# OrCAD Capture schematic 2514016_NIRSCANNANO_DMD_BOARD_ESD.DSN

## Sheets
1 PAGE-01  TITLE: title: ESD, Mobile Spectroscopy DMD Board
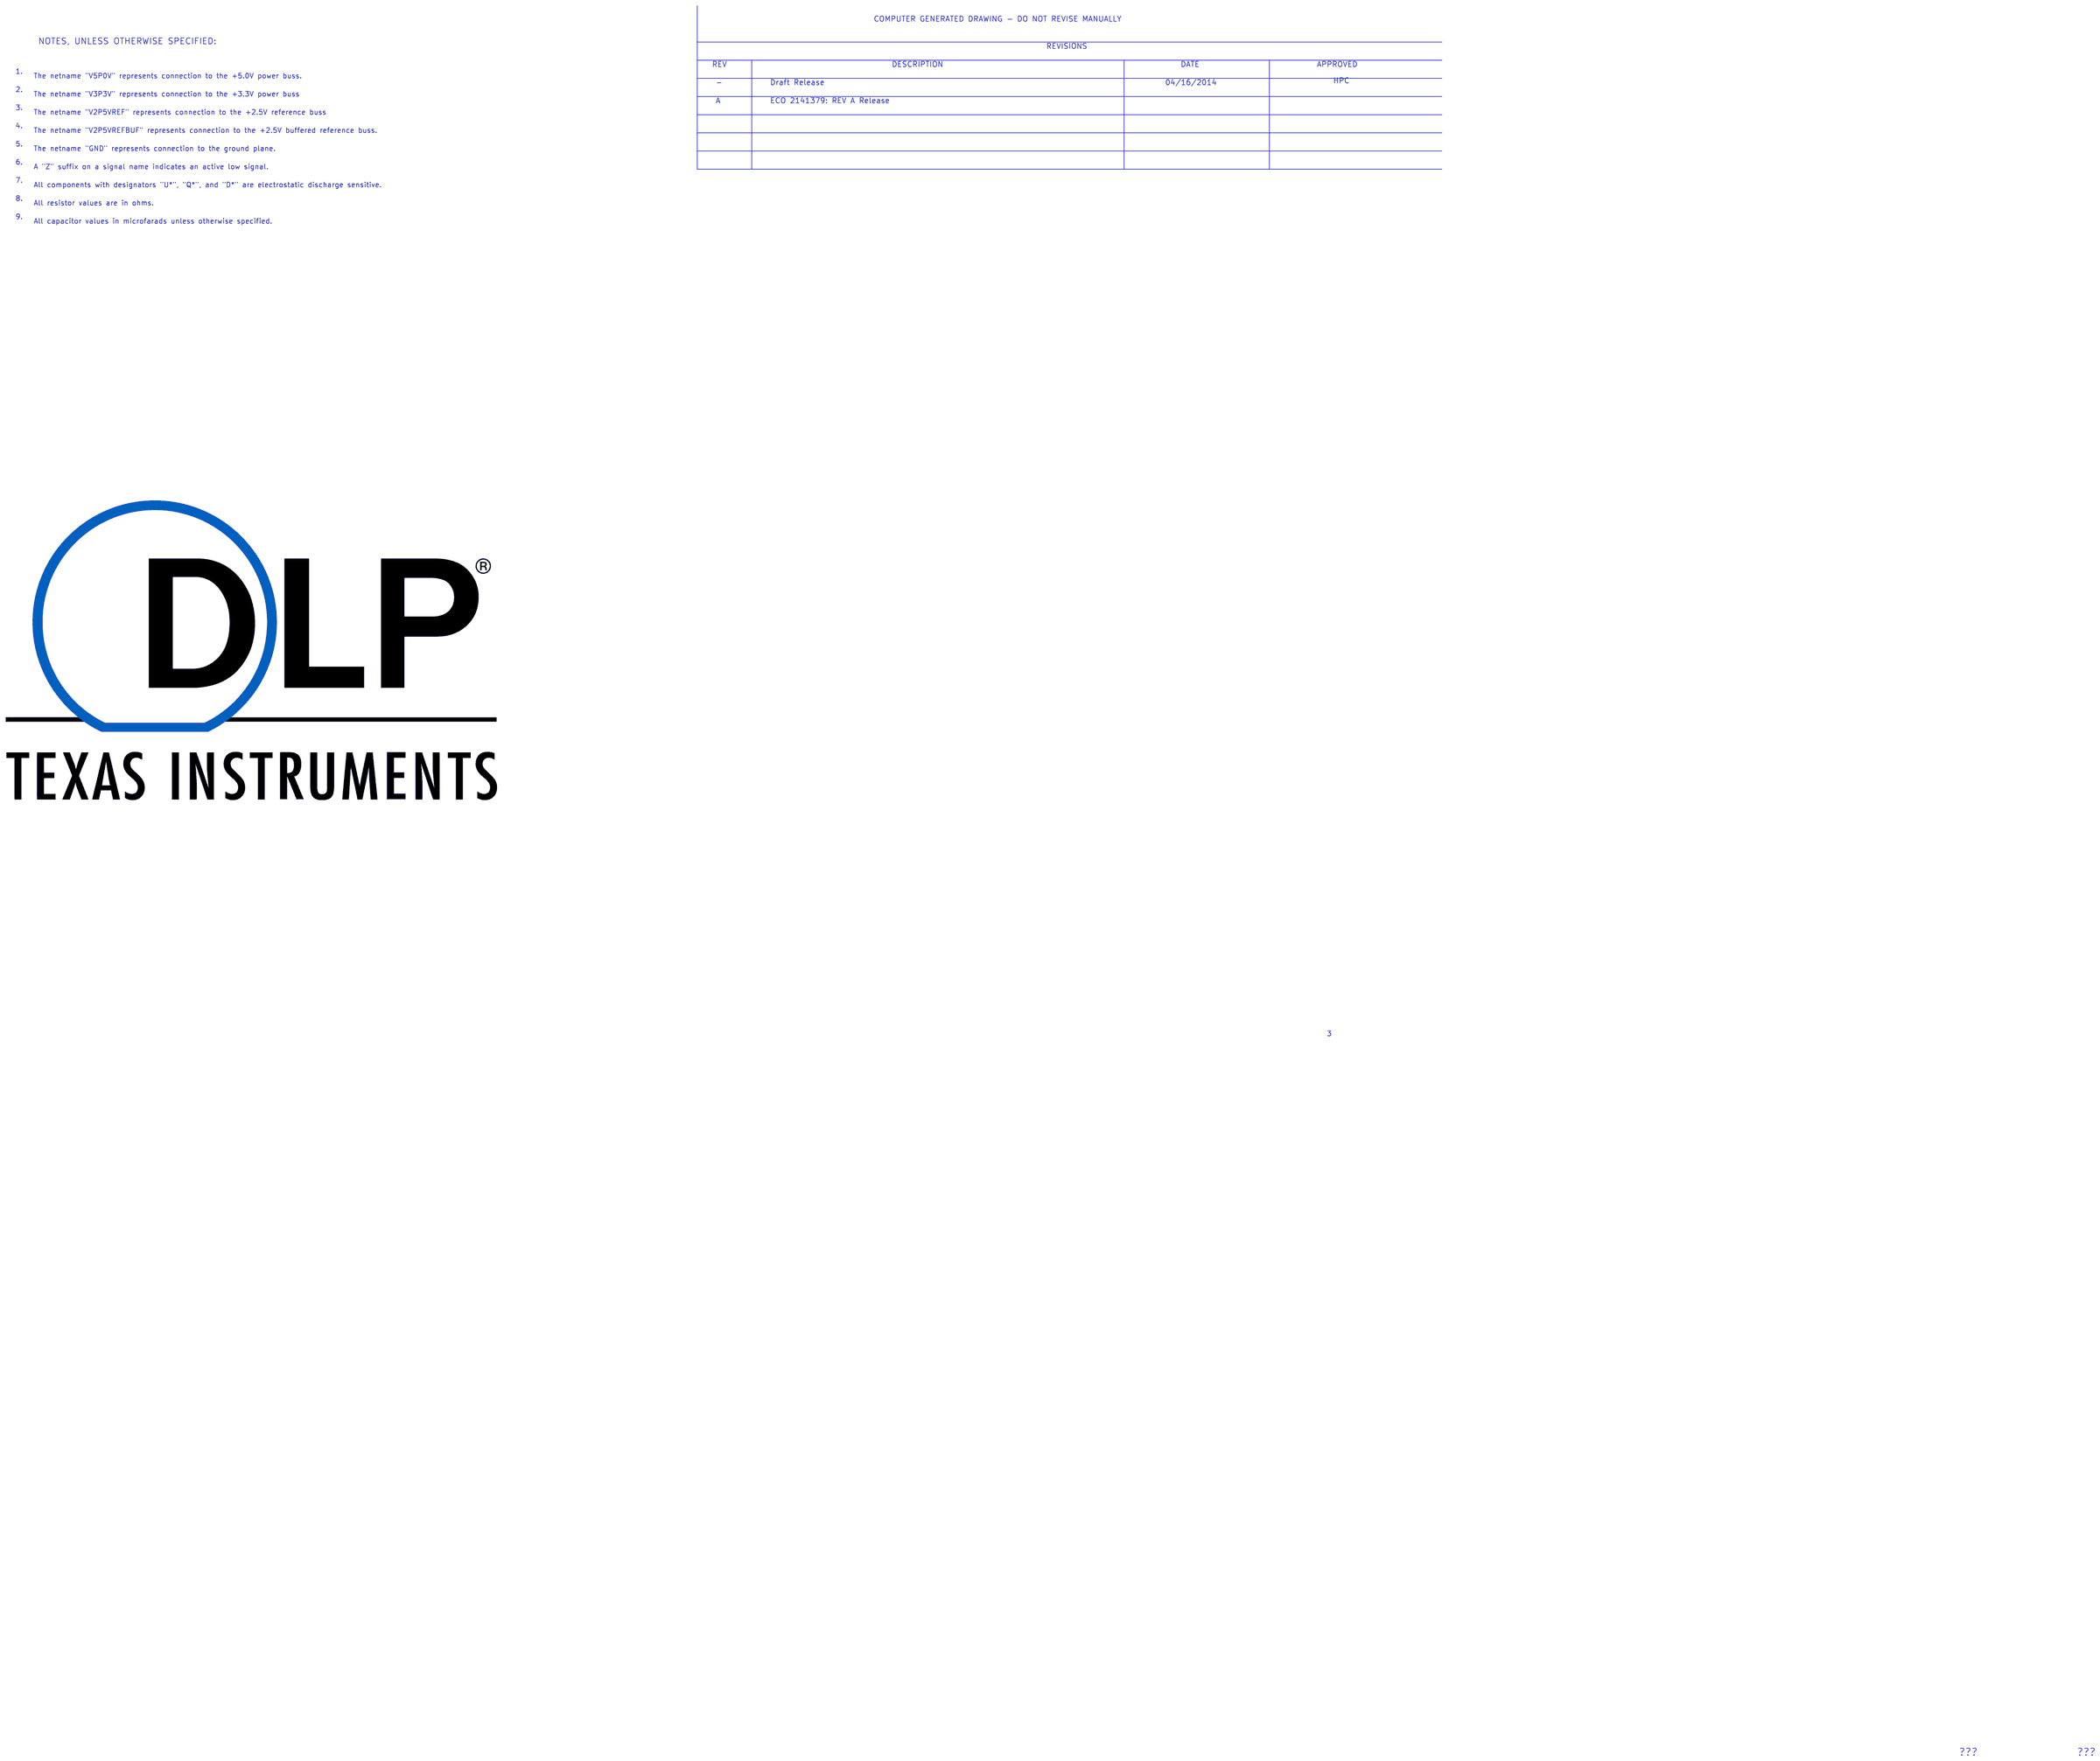
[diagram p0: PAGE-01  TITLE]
2 PAGE-02 s244 WVGA DMD: size A3
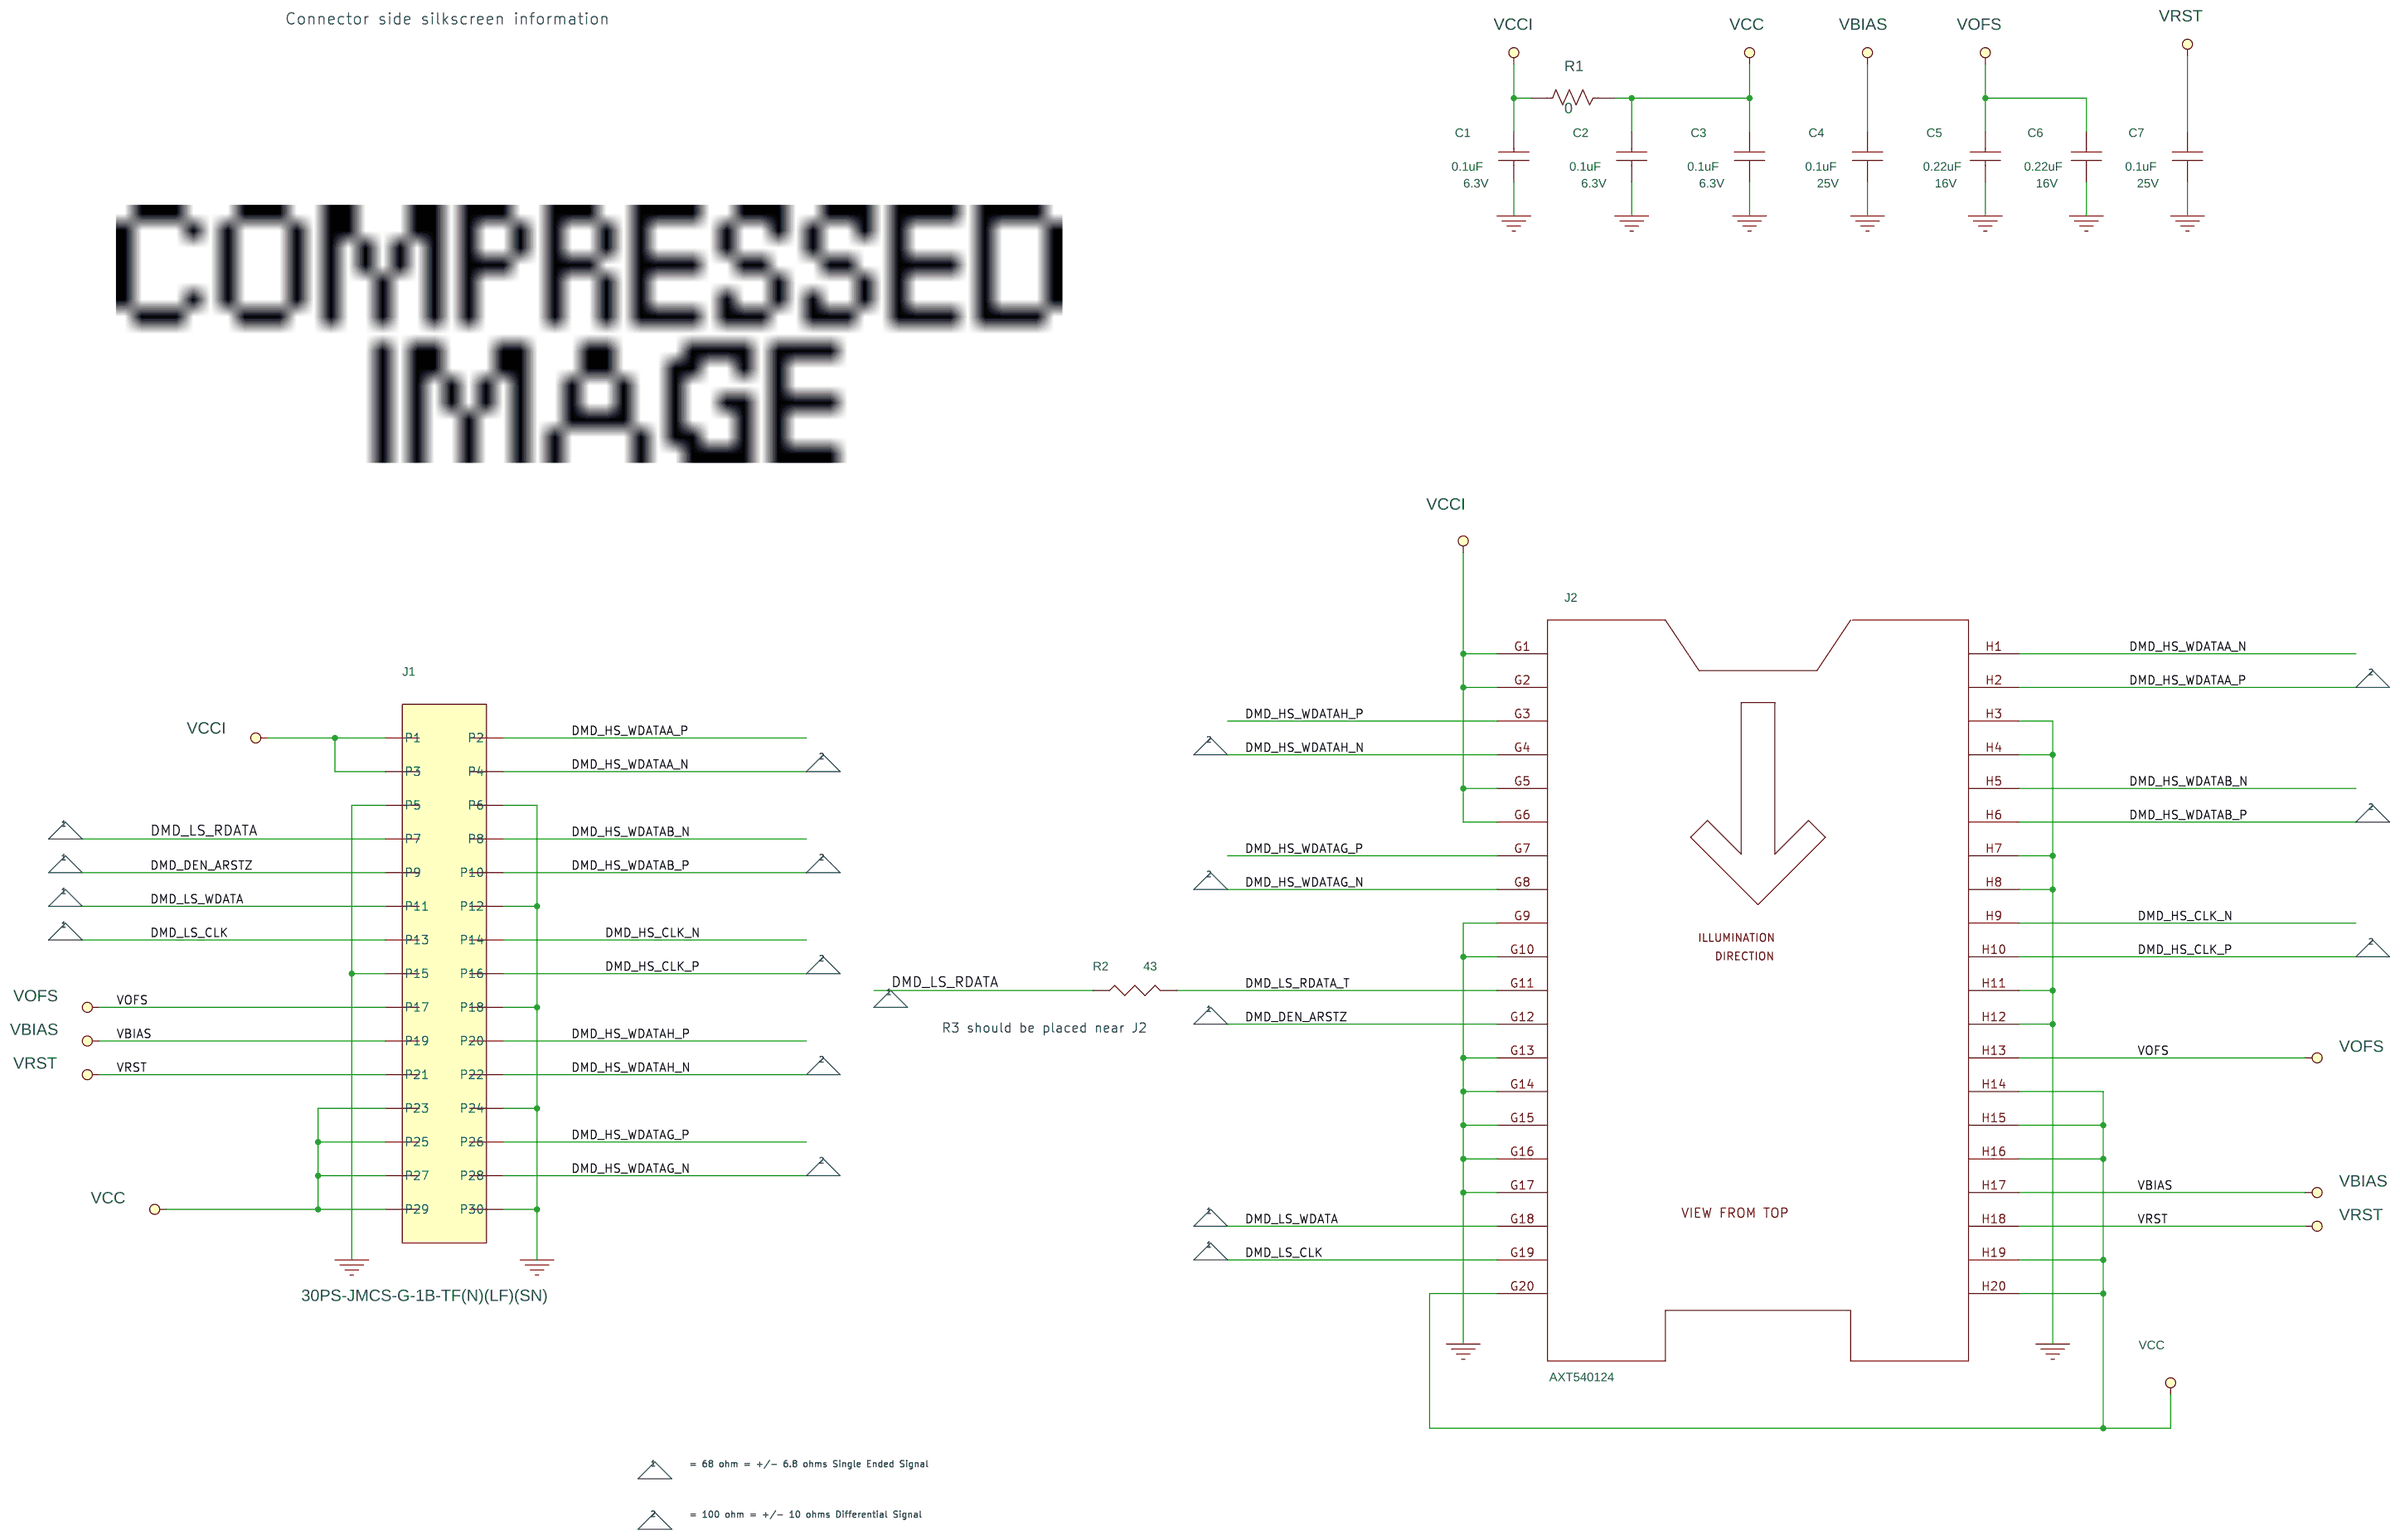
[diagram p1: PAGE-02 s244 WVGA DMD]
3 PAGE-3  REVISION HISTORY
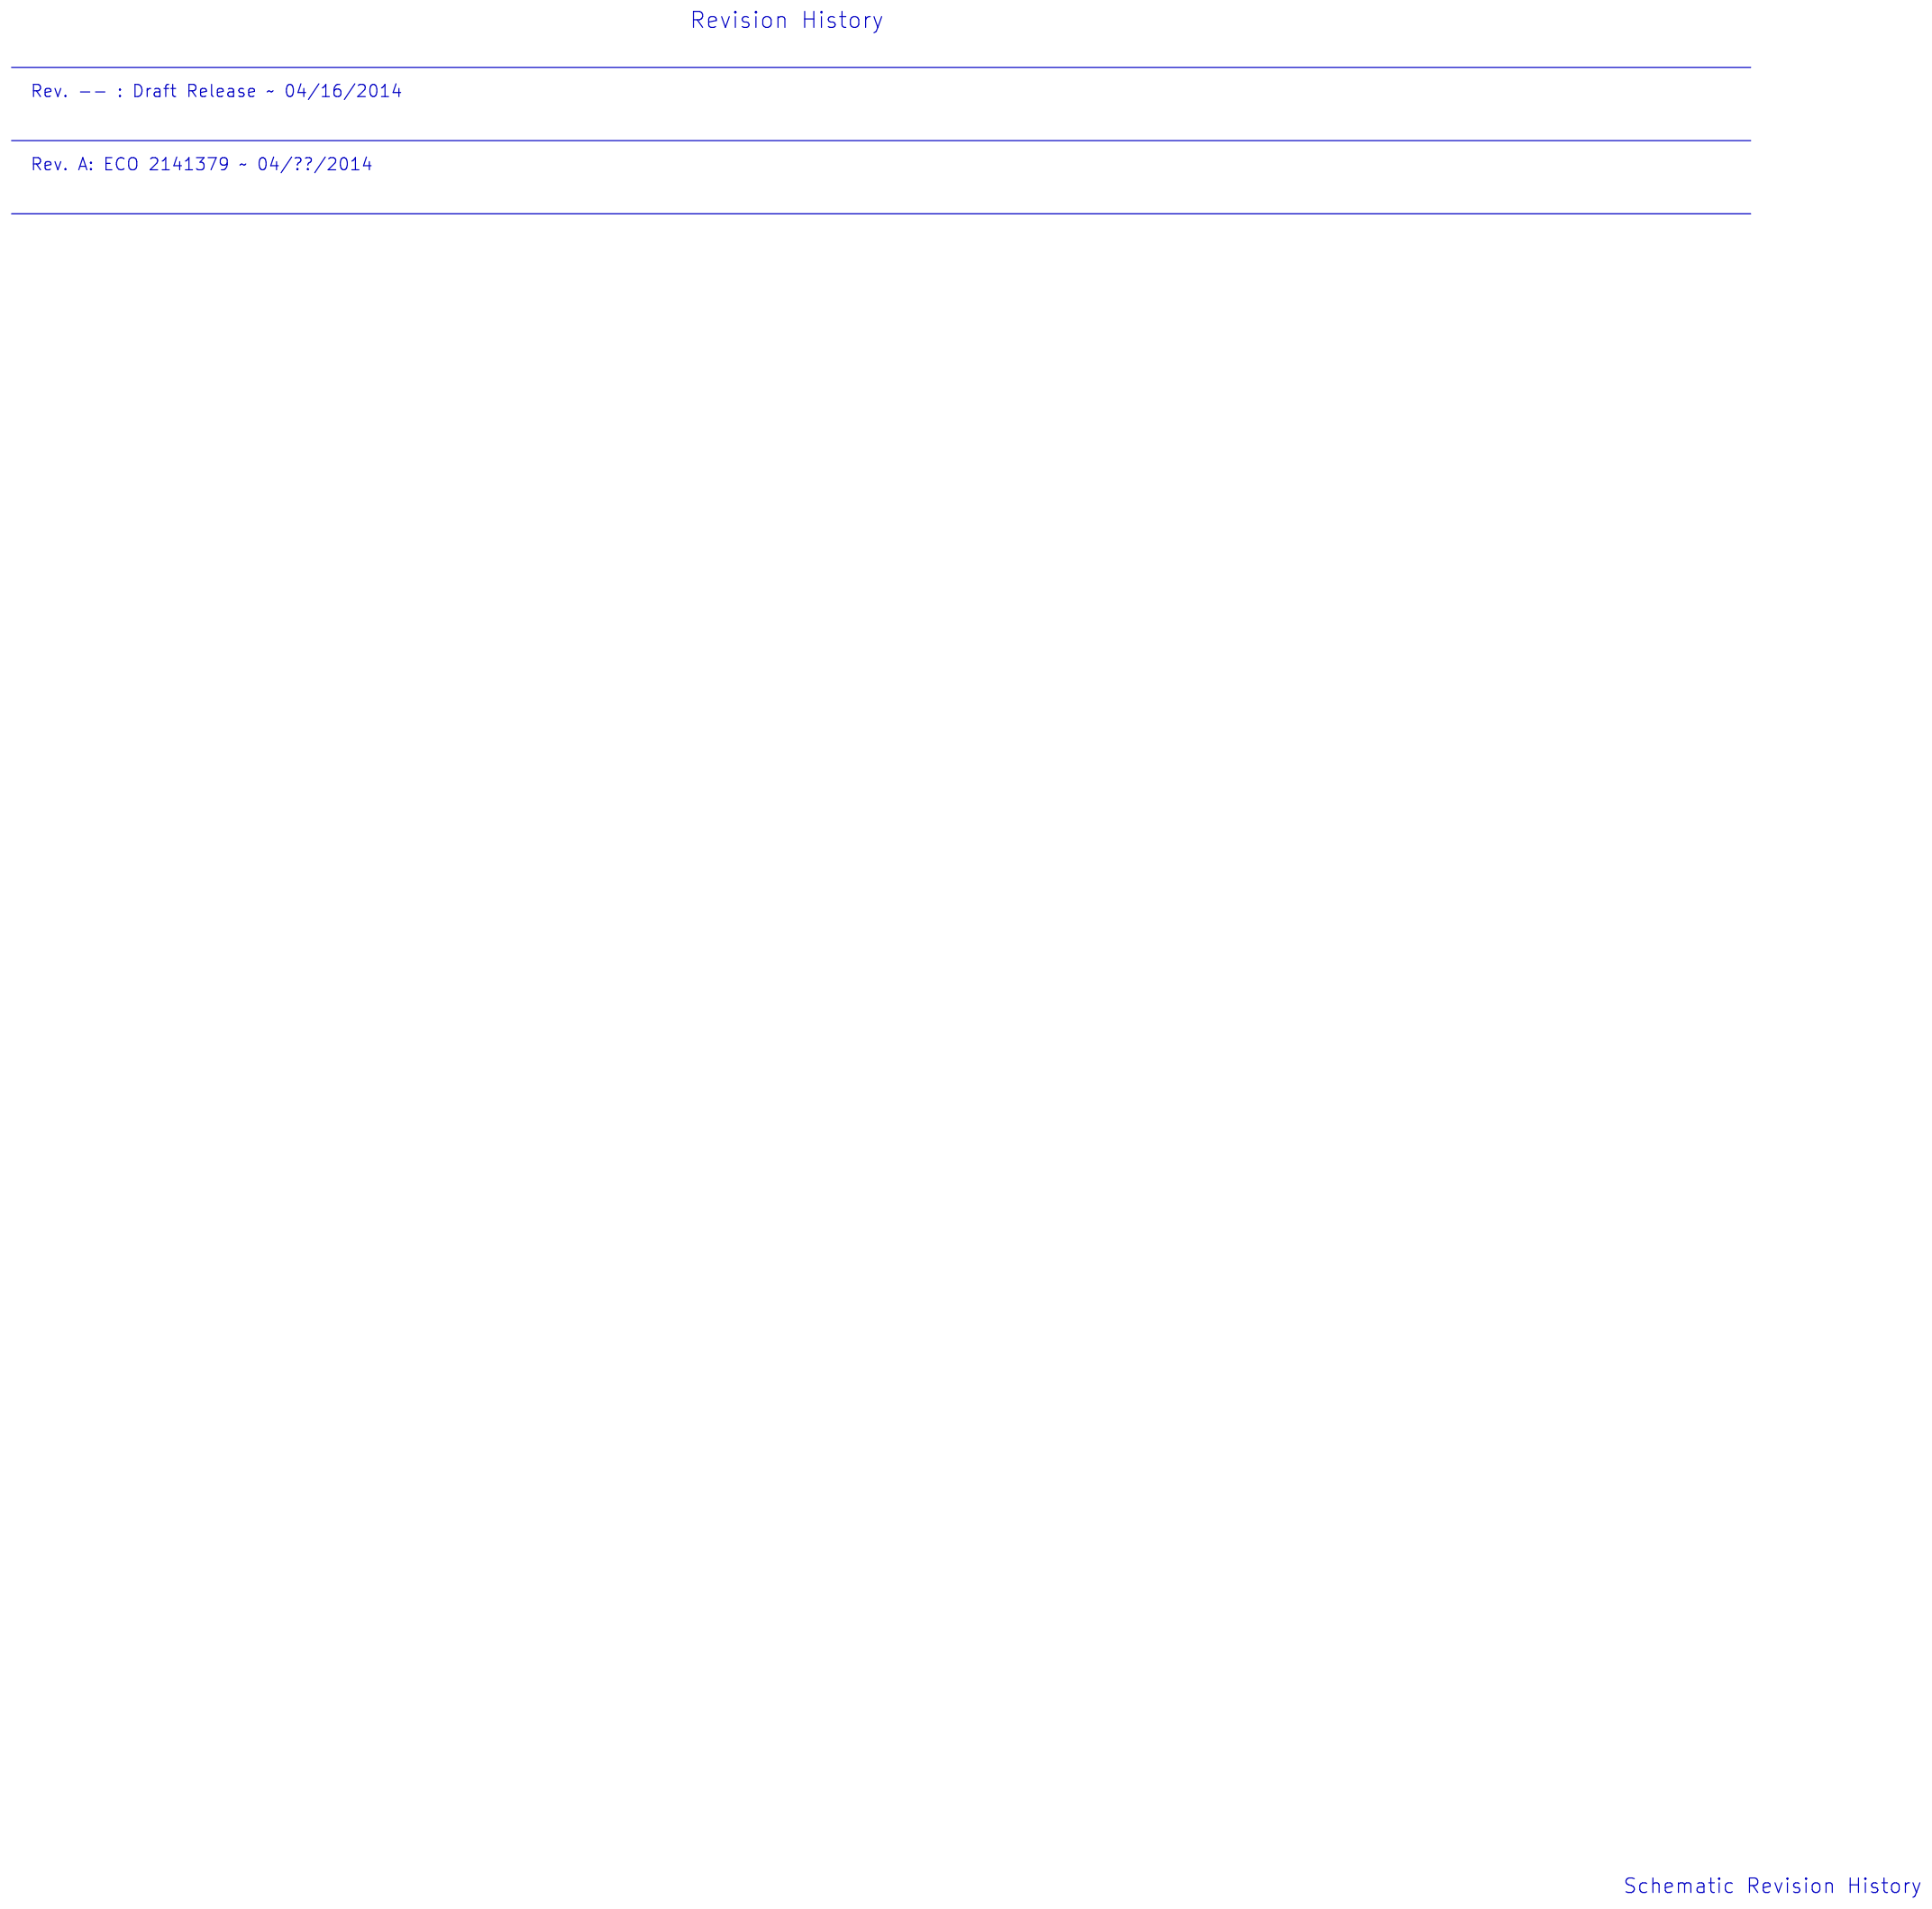
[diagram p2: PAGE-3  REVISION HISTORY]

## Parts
C1  0.1uF  [CAP_0201]
C2  0.1uF  [CAP_0201]
C3  0.1uF  [CAP_0201]
C4  0.1uF  [CAP_0402]
C5  0.22uF  [CAP_0201]
C6  0.22uF  [CAP_0201]
C7  0.1uF  [CAP_0402]
J1  30PS-JMCS-G-1B-TF(N)(LF)(SN)  [CONN30_2x15]
J2  AXT540124  [AXT542124]
R1  0  [RES_0201]
R2  43  [RES_0201]

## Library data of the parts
C1-C3 = CAP_NP: CAP CERAMIC 0.1UF 6.3V 10% X5R 0201; MFG: Murata; Manufacturer: Murata; Manufacturer Part Number: GRM033R60J104KE19D; Part Number: GRM033R60J104KE19D; RATING: 6.3V; SOURCE: DIGI 490-3167-1-ND; TOLERANCE: 10%; Type: X5R; VENDOR: Murata; VPC: 6.3V
C4 C7 = CAP_NP: CAP CERAMIC .1UF 25V 10% X5R 0402; Manufacturer: TDK; Manufacturer Part Number: C1005X5R1E104K050BC; Part Number: C1005X5R1E104K050BC; RATING: 25V; SOURCE: DIGI 445-4964-1-ND; TOLERANCE: 10%; Type: X5R
C5 C6 = CAP_NP: CAP CERAMIC 0.22UF 16V 20% X5R 0201; MFG: TDK; Manufacturer: TDK; Manufacturer Part Number: C0603X5R1C224M030BC; Part Number: C0603X5R1C224M030BC; RATING: 16V; SOURCE: DIGI 445-5927-1-ND; TOLERANCE: 20%; Type: X5R
J1 = CONN30_2x15: CONN 30POS PLUG W/BOSSES; Manufacturer: JST; SOURCE: DIGI 455-2845CT-ND
J2 = CONN,AXT540124,S244: CONN SOCKET F4S .4MM 40POS SMD; Manufacturer: PANASONIC; SOURCE: DIGI 255-2409-1-ND; VENDOR: PANASONIC
R1 = PAS,R,large: RES 0.0 OHM 1/20W 0201 SMD; DigiKey: P0.0AGCT-ND; DigiReel: P0.0AGDKR-ND; Family: passive; Index PN: 1178; Lead Style: SMT; MFG: PANASONIC; Manufacturer: PANASONIC; Manufacturer Part Number: ERJ-1GEJ430C; Material: chip; P/D_NUM: ERJ-1GE0R00C; Part Number: ERJ-1GE0R00C; Part Specific: RES 0.0 OHM 1/20W 0201 SMD; SOURCE: DIGI P0.0AGCT-ND; Type: resistor; VPC: 1/20W; Vendor: Panasonic
R2 = 1KR2F: RES 43 OHM 1/20W 5% 0201 SMD; MFG: PANASONIC; Manufacturer: PANASONIC; Manufacturer Part Number: ERJ-1GEJ430C; Part Number: ERJ-1GEJ430C; RATING: 1/16W; SOURCE: DIGI P43AGCT-ND; TOLERANCE: 5%

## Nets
GND: C1.2 C2.2 C3.2 C4.2 C5.2 C6.2 C7.2 J1.5(P5) J1.6(P6) J1.12(P12) J1.15(P15) J1.18(P18) J1.24(P24) J1.30(P30) J2.G9 J2.G10 J2.G13 J2.G14 J2.G15 J2.G16 J2.G17 J2.H3 J2.H4 J2.H7 J2.H8 J2.H11 J2.H12
VCC: C2.1 C3.1 J1.23(P23) J1.25(P25) J1.27(P27) J1.29(P29) J2.G20 J2.H14 J2.H15 J2.H16 J2.H19 J2.H20 R1.2(N2)
VCCI: C1.1 J1.1(P1) J1.3(P3) J2.G1 J2.G2 J2.G5 J2.G6 R1.1(N1)
DMD_DEN_ARSTZ: J1.9(P9) J2.G12
DMD_HS_CLK_N: J1.14(P14) J2.H9
DMD_HS_CLK_P: J1.16(P16) J2.H10
DMD_HS_WDATAA_N: J1.4(P4) J2.H1
DMD_HS_WDATAA_P: J1.2(P2) J2.H2
DMD_HS_WDATAB_N: J1.8(P8) J2.H5
DMD_HS_WDATAB_P: J1.10(P10) J2.H6
DMD_HS_WDATAG_N: J1.28(P28) J2.G8
DMD_HS_WDATAG_P: J1.26(P26) J2.G7
DMD_HS_WDATAH_N: J1.22(P22) J2.G4
DMD_HS_WDATAH_P: J1.20(P20) J2.G3
DMD_LS_CLK: J1.13(P13) J2.G19
DMD_LS_RDATA: J1.7(P7) R2.1
DMD_LS_RDATA_T: J2.G11 R2.2
DMD_LS_WDATA: J1.11(P11) J2.G18
VBIAS: C4.1 J1.19(P19) J2.H17
VOFS: C5.1 C6.1 J1.17(P17) J2.H13
VRST: C7.1 J1.21(P21) J2.H18

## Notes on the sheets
sheet 1
- COMPUTER GENERATED DRAWING - DO NOT REVISE MANUALLY
- NOTES, UNLESS OTHERWISE SPECIFIED:
- REVISIONS
- REV
- DESCRIPTION
- DATE
- APPROVED
- 1.
- The netname "V5P0V" represents connection to the +5.0V power buss.
- -
- Draft Release
- 04/16/2014
- HPC
- 2.
- The netname "V3P3V" represents connection to the +3.3V power buss
- 3.
- A
- ECO 2141379: REV A Release
- The netname "V2P5VREF" represents connection to the +2.5V reference buss
- 4.
- The netname "V2P5VREFBUF" represents connection to the +2.5V buffered reference buss.
- 5.
- The netname "GND" represents connection to the ground plane.
- 6.
- A "Z" suffix on a signal name indicates an active low signal.
- 7.
- All components with designators "U*", "Q*", and "D*" are electrostatic discharge sensitive.
- 8.
- All resistor values are in ohms.
- 9.
- All capacitor values in microfarads unless otherwise specified.
- 3
- ???
- ???
sheet 2
- Connector side silkscreen information
- 2
- 2
- 2
- 2
- 1
- 1
- 2
- 2
- 1
- 1
- 2
- 2
- 1
- 1
- R3 should be placed near J2
- 2
- 2
- 1
- 1
- 1
- = 68 ohm = +/- 6.8 ohms Single Ended Signal
- 2
- = 100 ohm = +/- 10 ohms Differential Signal
sheet 3
- Revision History
- Rev. -- : Draft Release ~ 04/16/2014
- Rev. A: ECO 2141379 ~ 04/??/2014
- Schematic Revision History
